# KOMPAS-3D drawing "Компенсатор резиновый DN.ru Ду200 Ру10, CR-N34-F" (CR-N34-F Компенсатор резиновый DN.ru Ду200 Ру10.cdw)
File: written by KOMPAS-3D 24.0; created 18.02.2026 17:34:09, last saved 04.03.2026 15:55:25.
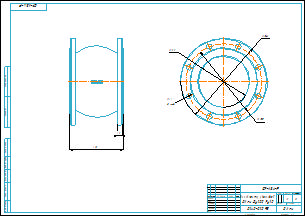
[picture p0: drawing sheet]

Document properties: Типовые: Типовые; Автор: DN.RU; Форматы листов документа: A2; Полное имя файла: CR-N34-F Компенсатор резиновый DN.ru Ду200 Ру10.m3d; Масса: 20; Наименование: Компенсатор резиновый DN.ru Ду200 Ру10; Количество листов документа: 1; Комментарий: D140-02095; Примечание: D140-02095

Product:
- Body: Твердое тело2  | qty 1
    Масса: 47.364795
- Part/product: Компенсатор резиновый DN.ru Ду200 Ру10  | designation CR-N34-F
    Масса: 20
    Раздел спецификации: Прочие изделия
    Комментарий: D140-02095
    Примечание: D140-02095
    additional columns: Типовые

Views: Вид 1, Справа, Проекционный вид 2
Referenced files in E:\Работа\Зайцев\CR-N34-F Компенсатор резиновый DN.ru ДУ25-300 Ру10-16\DN200_PN10\: CR-N34-F Компенсатор резиновый DN.ru Ду200 Ру10.m3d
Referenced files in E:\Работа\Зайцев\Для компаса\: чертеж DN.ru А3.cdt
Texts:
  CR-N34-F
  чертеж DN.ru А3.cdt
  Компенсатор резиновый
  DN.ru Ду200 Ру10
  Твердое тело2
  Компенсатор резиновый DN.ru Ду200 Ру10
  CR-N34-F Компенсатор резиновый DN.ru Ду200 Ру10
Dimensions and other numbers on the sheet: 0; 3; 2; 4; 210; 20; 340; 295; 200; 22; 8 отв.; 1:2; 1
